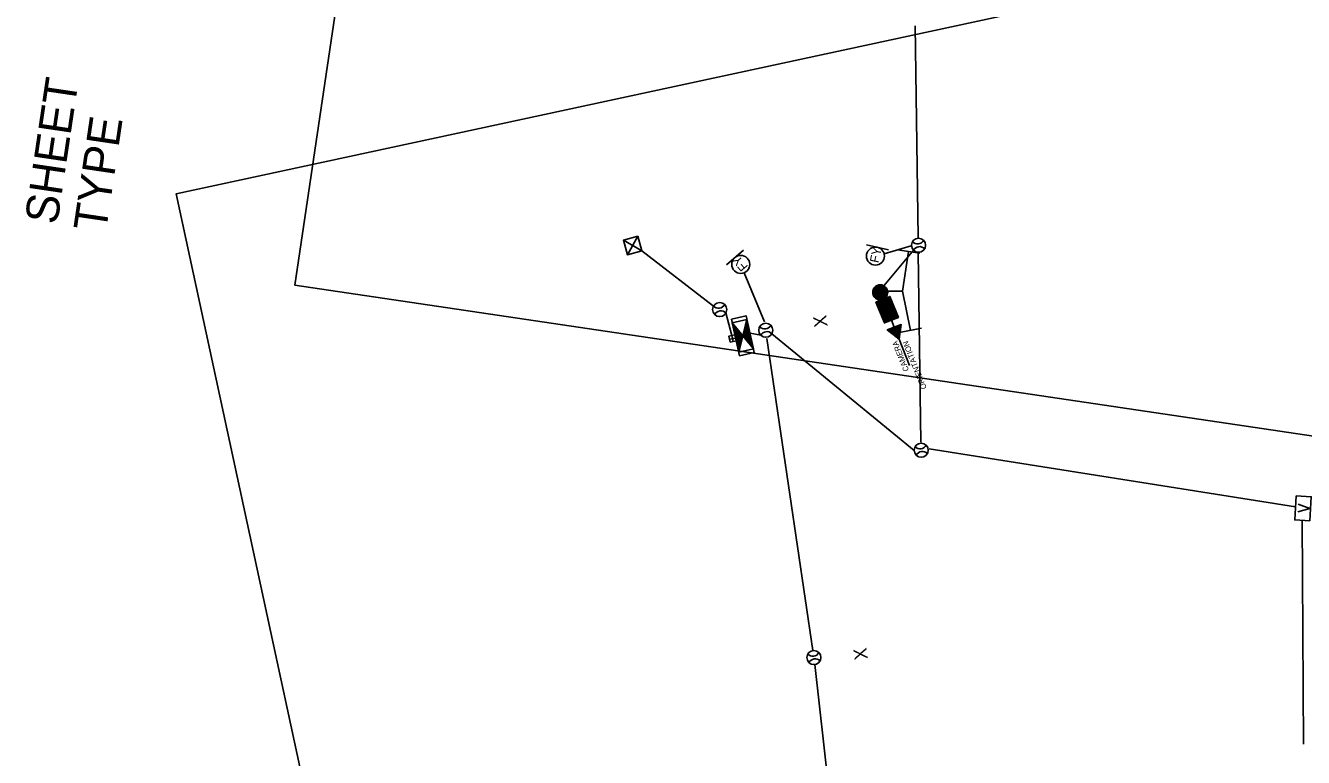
# Model space of a CAD drawing. Extents: x 601462 to 605493, y 331960 to 402715.
# Drawn here: x 601462 to 602143, y 355203 to 355593 of the extents above; entities that cross this region are included whole.
import ezdxf

# ---------------------------------------------------------------- set-up
doc = ezdxf.new("R2010")
doc.units = 0
for name, color, linetype in [('Default', 7, 'Continuous'), ('P_FTMS', 7, 'Continuous'), ('P_FTMSConduit', 7, 'Continuous'), ('P_MISC_TXT_1A', 7, 'Continuous'), ('P_MISC_TXT_2A (Construction)', 7, 'Continuous'), ('P_MISC_TXT_2B (Construction)', 7, 'Continuous')]:
    doc.layers.add(name, color=color, linetype=linetype)

# ---------------------------------------------------------------- blocks, each defined once
blk = doc.blocks.new('FMB_1')
at = {"layer": 'P_FTMS'}
for p, q in [((24.4, -24.4), (-24.4, 24.4)), ((-24.4, -24.4), (24.4, 24.4))]:
    blk.add_line(p, q, dxfattribs=at)
blk.add_lwpolyline([(24.4, -24.4), (24.4, 24.4), (-24.4, 24.4), (-24.4, -24.4)], close=True, dxfattribs=at)
blk = doc.blocks.new('POINT_DISPLAY')
at = {"layer": 'Default'}
blk.add_line((0, 0), (0, 0), dxfattribs=at)
blk = doc.blocks.new('FCS')
at = {"layer": 'P_FTMS'}
for p, q in [((-92.7, 0), (0, 0)), ((1.3, -0.8), (4.9, 2.8)), ((4.9, -2.8), (1.3, 0.8)), ((2.6, -1.5), (9.8, 5.7)), ((9.8, -5.7), (2.6, 1.5)), ((3.9, -2.3), (14.7, 8.5)), ((14.7, -8.5), (3.9, 2.3)), ((5.2, -3), (19.6, 11.3)), ((19.6, -11.3), (5.2, 3)), ((6.6, -3.8), (24.5, 14.1)), ((24.5, -14.2), (6.6, 3.8)), ((7.9, -4.5), (29.4, 17)), ((29.4, -17), (7.9, 4.5)), ((9.2, -5.3), (34.3, 19.8)), ((34.3, -19.8), (9.2, 5.3)), ((10.5, -6.1), (39.2, 22.6)), ((39.2, -22.6), (10.5, 6.1)), ((11.8, -6.8), (42, 23.4)), ((42, -23.4), (11.8, 6.8)), ((13.1, -7.6), (42, 21.3)), ((42, -21.3), (13.1, 7.6)), ((14.4, -8.3), (42, 19.3)), ((42, -19.3), (14.4, 8.3)), ((15.7, -9.1), (42, 17.2)), ((42, -17.2), (15.7, 9.1)), ((17, -9.8), (42, 15.1)), ((42, -15.1), (17.1, 9.8)), ((18.4, -10.6), (42, 13.1)), ((42, -13.1), (18.4, 10.6)), ((42, -11), (19.7, 11.4)), ((19.7, -11.4), (42, 11)), ((42, -8.9), (21, 12.1)), ((21, -12.1), (42, 8.9)), ((42, -6.8), (22.3, 12.9)), ((22.3, -12.9), (42, 6.8)), ((42, -4.8), (23.6, 13.6)), ((23.6, -13.6), (42, 4.8)), ((42, -2.7), (24.9, 14.4)), ((24.9, -14.4), (42, 2.7)), ((42, -0.6), (26.2, 15.1)), ((26.2, -15.2), (42, 0.6)), ((42, 1.4), (27.5, 15.9)), ((42, 3.5), (28.9, 16.7)), ((42, 5.6), (30.2, 17.4)), ((42, 7.6), (31.5, 18.2)), ((42, 9.7), (32.8, 18.9)), ((42, 11.8), (34.1, 19.7)), ((42, 13.8), (35.4, 20.4)), ((42, 15.9), (36.7, 21.2)), ((42, 18), (38, 22)), ((42, 20.1), (39.3, 22.7)), ((42, 22.1), (40.7, 23.5)), ((42, 24.2), (42, 24.2)), ((66.4, 0.1), (42, 0.1)), ((66.4, -24.3), (115.2, 24.5)), ((66.4, -13.9), (104.8, 24.5)), ((66.4, -3.6), (94.5, 24.5)), ((66.4, 6.8), (84.1, 24.5)), ((66.4, 17.1), (73.8, 24.5)), ((66.4, -22.2), (113.1, 24.5)), ((66.4, -11.9), (102.8, 24.5)), ((66.4, -1.5), (92.4, 24.5)), ((66.4, 8.8), (82.1, 24.5)), ((66.4, 19.2), (71.7, 24.5)), ((66.4, -20.1), (111, 24.5)), ((66.4, -9.8), (100.7, 24.5)), ((66.4, 0.6), (90.3, 24.5)), ((66.4, 10.9), (80, 24.5)), ((66.4, 21.2), (69.6, 24.5)), ((66.4, -18.1), (109, 24.5)), ((66.4, -7.7), (98.6, 24.5)), ((66.4, 2.6), (88.3, 24.5)), ((66.4, 13), (77.9, 24.5)), ((66.4, 23.3), (67.6, 24.5)), ((66.4, -16), (106.9, 24.5)), ((66.4, -5.7), (96.5, 24.5)), ((66.4, 4.7), (86.2, 24.5)), ((66.4, 15), (75.9, 24.5)), ((114, -24.3), (66.4, 23.3)), ((111.9, -24.3), (66.4, 21.2)), ((109.9, -24.3), (66.4, 19.2)), ((107.8, -24.3), (66.4, 17.1)), ((105.7, -24.3), (66.4, 15)), ((103.6, -24.3), (66.4, 13)), ((101.6, -24.3), (66.4, 10.9)), ((99.5, -24.3), (66.4, 8.8)), ((97.4, -24.3), (66.4, 6.8)), ((95.4, -24.3), (66.4, 4.7)), ((93.3, -24.3), (66.4, 2.6)), ((91.2, -24.3), (66.4, 0.6)), ((116.1, -24.3), (67.3, 24.5)), ((68.5, -24.3), (117.2, 24.5)), ((118.1, -24.3), (69.4, 24.5)), ((70.5, -24.3), (119.3, 24.5)), ((120.2, -24.3), (71.4, 24.5)), ((72.6, -24.3), (121.4, 24.5)), ((122.3, -24.3), (73.5, 24.5)), ((74.7, -24.3), (123.4, 24.5)), ((124.3, -24.3), (75.6, 24.5)), ((76.7, -24.3), (125.5, 24.5)), ((126.4, -24.3), (77.6, 24.5)), ((78.8, -24.3), (127.6, 24.5)), ((128.5, -24.3), (79.7, 24.5)), ((80.9, -24.3), (129.7, 24.5)), ((130.5, -24.3), (81.8, 24.5)), ((83, -24.3), (131.7, 24.5)), ((132.6, -24.3), (83.8, 24.5)), ((85, -24.3), (133.8, 24.5)), ((134.7, -24.3), (85.9, 24.5)), ((87.1, -24.3), (135.9, 24.5)), ((136.7, -24.3), (88, 24.5)), ((89.2, -24.3), (137.9, 24.5)), ((138.8, -24.3), (90.1, 24.5)), ((91.2, -24.3), (139.6, 24.1)), ((139.6, -22.9), (92.1, 24.5)), ((93.3, -24.3), (139.6, 22)), ((139.6, -20.9), (94.2, 24.5)), ((95.4, -24.3), (139.6, 19.9)), ((139.6, -18.8), (96.3, 24.5)), ((97.4, -24.3), (139.6, 17.8)), ((139.6, -16.7), (98.3, 24.5)), ((99.5, -24.3), (139.6, 15.8)), ((139.6, -14.7), (100.4, 24.5)), ((101.6, -24.3), (139.6, 13.7)), ((139.6, -12.6), (102.5, 24.5)), ((103.6, -24.3), (139.6, 11.6)), ((139.6, -10.5), (104.5, 24.5)), ((105.7, -24.3), (139.6, 9.6)), ((139.6, -8.5), (106.6, 24.5)), ((107.8, -24.3), (139.6, 7.5)), ((139.6, -6.4), (108.7, 24.5)), ((109.9, -24.3), (139.6, 5.4)), ((110.4, 0.1), (112, 0.1)), ((139.6, -4.3), (110.7, 24.5)), ((111.9, -24.3), (139.6, 3.4)), ((139.6, -2.3), (112.8, 24.5)), ((114, -24.3), (139.6, 1.3)), ((139.6, -0.2), (114.9, 24.5)), ((139.6, 1.9), (116.9, 24.5)), ((139.6, 4), (119, 24.5)), ((139.6, 6), (121.1, 24.5)), ((139.6, 8.1), (123.2, 24.5)), ((139.6, 10.2), (125.2, 24.5)), ((139.6, 12.2), (127.3, 24.5)), ((139.6, 14.3), (129.4, 24.5)), ((139.6, 16.4), (131.4, 24.5)), ((139.6, 18.4), (133.5, 24.5)), ((139.6, 20.5), (135.6, 24.5)), ((139.6, 22.6), (137.6, 24.5)), ((139.6, 0.6), (163.5, 24.4)), ((165.5, -24.2), (139.6, 1.6)), ((139.7, -1.4), (165.4, 24.4)), ((139.8, 2.9), (161.2, 24.3)), ((139.8, -3.3), (167.3, 24.2)), ((167.3, -24), (139.9, 3.5)), ((140.1, 5.2), (158.7, 23.9)), ((169.1, -23.7), (140.1, 5.3)), ((140.2, -5), (169.1, 23.9)), ((140.6, -6.7), (170.7, 23.4)), ((170.8, -23.3), (140.6, 6.9)), ((141, 8.2), (155.9, 23.1)), ((141.1, -8.2), (172.3, 23)), ((172.3, -22.7), (141.1, 8.5)), ((141.7, -9.7), (173.8, 22.3)), ((173.8, -22.2), (141.7, 9.9)), ((142.3, -11.1), (175.2, 21.7)), ((175.2, -21.5), (142.4, 11.3)), ((142.7, 12), (152.2, 21.5)), ((143.1, -12.4), (176.5, 20.9)), ((176.5, -20.7), (143.1, 12.7)), ((143.9, -13.7), (177.7, 20.1)), ((177.8, -19.9), (143.9, 13.9)), ((144.8, -14.9), (179, 19.3)), ((178.9, -19), (144.8, 15.1)), ((180.1, -18.1), (145.7, 16.3)), ((145.8, -16), (180.1, 18.3)), ((146.7, -17.1), (181.1, 17.3)), ((181.2, -17.1), (146.8, 17.3)), ((182.1, -16), (147.8, 18.3)), ((147.8, -18.1), (182.2, 16.3)), ((183.1, -14.9), (148.9, 19.3)), ((149, -19), (183.1, 15.1)), ((184, -13.7), (150.1, 20.1)), ((150.1, -19.9), (184, 13.9)), ((184.8, -12.4), (151.4, 20.9)), ((151.4, -20.7), (184.8, 12.7)), ((185.5, -11.2), (152.7, 21.7)), ((152.7, -21.5), (185.5, 11.3)), ((186.2, -9.7), (154.1, 22.3)), ((154.1, -22.2), (186.2, 9.9)), ((186.8, -8.2), (155.6, 23)), ((155.6, -22.7), (186.8, 8.5)), ((157.1, -23.3), (187.3, 6.9)), ((187.3, -6.7), (157.2, 23.4)), ((187.7, -5), (158.8, 23.9)), ((158.8, -23.7), (187.8, 5.3)), ((188.1, -3.3), (160.5, 24.2)), ((160.6, -24), (188, 3.5)), ((188.2, -1.4), (162.4, 24.4)), ((162.4, -24.2), (188.2, 1.6)), ((188.3, 0.6), (164.4, 24.5)), ((188.1, 2.9), (166.7, 24.3)), ((187.8, 5.2), (169.2, 23.9)), ((186.9, 8.2), (172, 23.1)), ((185.2, 12), (175.7, 21.4)), ((27.5, -15.9), (42, -1.4)), ((28.9, -16.7), (42, -3.5)), ((30.2, -17.4), (42, -5.6)), ((31.5, -18.2), (42, -7.6)), ((32.8, -18.9), (42, -9.7)), ((34.1, -19.7), (42, -11.8)), ((35.4, -20.5), (42, -13.8)), ((36.7, -21.2), (42, -15.9)), ((38, -22), (42, -18)), ((39.3, -22.7), (42, -20.1)), ((40.7, -23.5), (42, -22.1)), ((42, -24.2), (42, -24.2)), ((89.2, -24.3), (66.4, -1.5)), ((87.1, -24.3), (66.4, -3.6)), ((85, -24.3), (66.4, -5.7)), ((83, -24.3), (66.4, -7.7)), ((80.9, -24.3), (66.4, -9.8)), ((78.8, -24.3), (66.4, -11.9)), ((76.7, -24.3), (66.4, -13.9)), ((74.7, -24.3), (66.4, -16)), ((72.6, -24.3), (66.4, -18.1)), ((70.5, -24.3), (66.4, -20.1)), ((68.5, -24.3), (66.4, -22.2)), ((116.1, -24.3), (139.6, -0.8)), ((118.1, -24.3), (139.6, -2.8)), ((120.2, -24.3), (139.6, -4.9)), ((122.3, -24.3), (139.6, -7)), ((124.3, -24.3), (139.6, -9.1)), ((126.4, -24.3), (139.6, -11.1)), ((128.5, -24.3), (139.6, -13.2)), ((130.5, -24.3), (139.6, -15.3)), ((132.6, -24.3), (139.6, -17.3)), ((134.7, -24.3), (139.6, -19.4)), ((136.7, -24.3), (139.6, -21.5)), ((138.8, -24.3), (139.6, -23.5)), ((163.4, -24.2), (139.6, -0.4)), ((161.2, -24.1), (139.7, -2.6)), ((158.7, -23.6), (140.2, -5.1)), ((155.8, -22.8), (141, -8)), ((152, -21), (142.7, -11.8)), ((164.5, -24.2), (188.2, -0.4)), ((166.7, -24.1), (188.1, -2.6)), ((169.2, -23.7), (187.7, -5.1)), ((172.1, -22.8), (186.9, -8)), ((175.9, -21), (185.2, -11.8))]:
    blk.add_line(p, q, dxfattribs=at)
for points in [[(42, -24.3), (42, 24.3), (0, 0)], [(139.6, 24.5), (66.4, 24.5), (66.4, -24.3), (139.6, -24.3)]]:
    blk.add_lwpolyline(points, close=True, dxfattribs=at)
blk.add_circle((163.9, 0.1), 24.4, dxfattribs=at)
for p in [(0, 0), (110.4, 0.1)]:
    blk.add_blockref('POINT_DISPLAY', p, dxfattribs=at)
at = {"layer": 'P_MISC_TXT_1A'}
for s, height, p in [('CAMERA', 18.29, (-105.8, 7)), ('ORIENTATION', 18.288, (-181.1, -25))]:
    blk.add_text(s, height=height, rotation=360, dxfattribs=at).set_placement(p)
blk = doc.blocks.new('FTMS_FCV')
at = {"layer": 'P_FTMS'}
blk.add_line((12.7, 16.3), (0.6, -21.9), dxfattribs=at)
blk.add_lwpolyline([(39.1, 24.4), (-39.1, 24.4), (-39.1, -24.4), (39.1, -24.4)], close=True, dxfattribs=at)
blk.add_lwpolyline([(-12.1, 16.2), (0.6, -21.9)], dxfattribs=at)
blk = doc.blocks.new('FTMS_FCB')
at = {"layer": 'P_FTMS'}
for p, q in [((-48.3, 24.1), (-48, 24.4)), ((-45.5, 22.7), (-47.1, 24.4)), ((-46.9, 23.4), (-46, 24.4)), ((-45.5, 22.8), (-43.9, 24.4)), ((-41.4, 20.7), (-45.1, 24.4)), ((-44.1, 22.1), (-41.8, 24.4)), ((-37.2, 18.6), (-43, 24.4)), ((-42.8, 21.4), (-39.8, 24.4)), ((-41.4, 20.7), (-37.7, 24.4)), ((-33.1, 16.5), (-40.9, 24.4)), ((-40, 20), (-35.6, 24.4)), ((-29, 14.5), (-38.9, 24.4)), ((-38.6, 19.3), (-33.6, 24.4)), ((-37.2, 18.6), (-31.5, 24.4)), ((-24.8, 12.4), (-36.8, 24.4)), ((-35.9, 17.9), (-29.4, 24.4)), ((-20.7, 10.3), (-34.7, 24.4)), ((-34.5, 17.2), (-27.3, 24.4)), ((-33.1, 16.5), (-25.3, 24.4)), ((-16.5, 8.3), (-32.7, 24.4)), ((-31.7, 15.9), (-23.2, 24.4)), ((-12.4, 6.2), (-30.6, 24.4)), ((-30.3, 15.2), (-21.1, 24.4)), ((-29, 14.5), (-19.1, 24.4)), ((-8.3, 4.1), (-28.5, 24.4)), ((-27.6, 13.8), (-17, 24.4)), ((-4.1, 2.1), (-26.4, 24.4)), ((-26.2, 13.1), (-14.9, 24.4)), ((-24.8, 12.4), (-12.9, 24.4)), ((0, 0), (-24.4, 24.4)), ((-24.4, -24.4), (0, 0)), ((-23.5, 11.7), (-10.8, 24.4)), ((1.4, 0.7), (-22.3, 24.4)), ((-22.1, 11), (-8.7, 24.4)), ((-20.7, 10.3), (-6.7, 24.4)), ((2.8, 1.4), (-20.2, 24.4)), ((-19.3, 9.7), (-4.6, 24.4)), ((4.1, 2.1), (-18.2, 24.4)), ((-17.9, 9), (-2.5, 24.4)), ((-16.6, 8.3), (-0.4, 24.4)), ((5.5, 2.8), (-16.1, 24.4)), ((-15.2, 7.6), (1.6, 24.4)), ((6.9, 3.4), (-14, 24.4)), ((-13.8, 6.9), (3.7, 24.4)), ((-12.4, 6.2), (5.8, 24.4)), ((8.3, 4.1), (-12, 24.4)), ((-11, 5.5), (7.8, 24.4)), ((9.7, 4.8), (-9.9, 24.4)), ((-9.7, 4.8), (9.9, 24.4)), ((-8.3, 4.1), (12, 24.4)), ((11, 5.5), (-7.8, 24.4)), ((-6.9, 3.4), (14, 24.4)), ((12.4, 6.2), (-5.8, 24.4)), ((-5.5, 2.8), (16.1, 24.4)), ((-4.1, 2.1), (18.2, 24.4)), ((13.8, 6.9), (-3.7, 24.4)), ((-2.8, 1.4), (20.2, 24.4)), ((15.2, 7.6), (-1.6, 24.4)), ((-1.4, 0.7), (22.3, 24.4)), ((0, 0), (24.4, 24.4)), ((24.4, -24.4), (0, 0)), ((16.6, 8.3), (0.4, 24.4)), ((17.9, 9), (2.5, 24.4)), ((4.1, 2.1), (26.5, 24.4)), ((19.3, 9.7), (4.6, 24.4)), ((20.7, 10.3), (6.7, 24.4)), ((8.3, 4.1), (28.5, 24.4)), ((22.1, 11), (8.7, 24.4)), ((23.4, 11.7), (10.8, 24.4)), ((12.4, 6.2), (30.6, 24.4)), ((24.8, 12.4), (12.9, 24.4)), ((26.2, 13.1), (14.9, 24.4)), ((16.6, 8.3), (32.7, 24.4)), ((27.6, 13.8), (17, 24.4)), ((29, 14.5), (19.1, 24.4)), ((20.7, 10.3), (34.7, 24.4)), ((30.3, 15.2), (21.1, 24.4)), ((31.7, 15.9), (23.2, 24.4)), ((24.8, 12.4), (36.8, 24.4)), ((33.1, 16.6), (25.3, 24.4)), ((34.5, 17.2), (27.3, 24.4)), ((29, 14.5), (38.9, 24.4)), ((35.9, 17.9), (29.4, 24.4)), ((37.2, 18.6), (31.5, 24.4)), ((33.1, 16.6), (40.9, 24.4)), ((38.6, 19.3), (33.5, 24.4)), ((40, 20), (35.6, 24.4)), ((37.2, 18.6), (43, 24.4)), ((41.4, 20.7), (37.7, 24.4)), ((42.8, 21.4), (39.8, 24.4)), ((41.4, 20.7), (45.1, 24.4)), ((44.1, 22.1), (41.8, 24.4)), ((45.5, 22.8), (43.9, 24.4)), ((45.5, 22.8), (47.1, 24.4)), ((46.9, 23.5), (46, 24.4)), ((48.3, 24.1), (48, 24.4)), ((-48, -24.4), (-48.3, -24.1)), ((-47.2, -24.4), (-45.5, -22.8)), ((-45.9, -24.4), (-46.9, -23.5)), ((-43.9, -24.4), (-45.5, -22.8)), ((-45.1, -24.4), (-41.4, -20.7)), ((-41.8, -24.4), (-44.1, -22.1)), ((-43, -24.4), (-37.3, -18.6)), ((-39.7, -24.4), (-42.8, -21.4)), ((-37.7, -24.4), (-41.4, -20.7)), ((-41, -24.4), (-33.1, -16.6)), ((-35.6, -24.4), (-40, -20)), ((-38.9, -24.4), (-29, -14.5)), ((-33.5, -24.4), (-38.6, -19.3)), ((-31.5, -24.4), (-37.2, -18.6)), ((-36.8, -24.4), (-24.8, -12.4)), ((-29.4, -24.4), (-35.9, -17.9)), ((-34.8, -24.4), (-20.7, -10.4)), ((-27.3, -24.4), (-34.5, -17.2)), ((-25.3, -24.4), (-33.1, -16.6)), ((-32.7, -24.4), (-16.6, -8.3)), ((-23.2, -24.4), (-31.7, -15.9)), ((-30.6, -24.4), (-12.4, -6.2)), ((-21.1, -24.4), (-30.3, -15.2)), ((-19, -24.4), (-29, -14.5)), ((-28.5, -24.4), (-8.3, -4.1)), ((-17, -24.4), (-27.6, -13.8)), ((-26.5, -24.4), (-4.1, -2.1)), ((-14.9, -24.4), (-26.2, -13.1)), ((-12.8, -24.4), (-24.8, -12.4)), ((-10.8, -24.4), (-23.4, -11.7)), ((-22.3, -24.4), (1.4, -0.7)), ((-8.7, -24.4), (-22.1, -11)), ((-6.6, -24.4), (-20.7, -10.3)), ((-20.3, -24.4), (2.8, -1.4)), ((-4.6, -24.4), (-19.3, -9.7)), ((-18.2, -24.4), (4.1, -2.1)), ((-2.5, -24.4), (-17.9, -9)), ((-0.4, -24.4), (-16.6, -8.3)), ((-16.1, -24.4), (5.5, -2.8)), ((1.6, -24.4), (-15.2, -7.6)), ((-14.1, -24.4), (6.9, -3.4)), ((3.7, -24.4), (-13.8, -6.9)), ((5.8, -24.4), (-12.4, -6.2)), ((-12, -24.4), (8.3, -4.1)), ((7.8, -24.4), (-11, -5.5)), ((-9.9, -24.4), (9.7, -4.8)), ((9.9, -24.4), (-9.7, -4.8)), ((12, -24.4), (-8.3, -4.1)), ((-7.8, -24.4), (11, -5.5)), ((14.1, -24.4), (-6.9, -3.5)), ((-5.8, -24.4), (12.4, -6.2)), ((16.1, -24.4), (-5.5, -2.8)), ((18.2, -24.4), (-4.1, -2.1)), ((-3.7, -24.4), (13.8, -6.9)), ((20.3, -24.4), (-2.8, -1.4)), ((-1.6, -24.4), (15.2, -7.6)), ((22.3, -24.4), (-1.4, -0.7)), ((0.4, -24.4), (16.6, -8.3)), ((2.5, -24.4), (17.9, -9)), ((26.5, -24.4), (4.1, -2.1)), ((4.6, -24.4), (19.3, -9.7)), ((6.6, -24.4), (20.7, -10.3)), ((28.5, -24.4), (8.3, -4.1)), ((8.7, -24.4), (22.1, -11)), ((10.8, -24.4), (23.4, -11.7)), ((30.6, -24.4), (12.4, -6.2)), ((12.8, -24.4), (24.8, -12.4)), ((14.9, -24.4), (26.2, -13.1)), ((32.7, -24.4), (16.6, -8.3)), ((17, -24.4), (27.6, -13.8)), ((19.1, -24.4), (29, -14.5)), ((34.7, -24.4), (20.7, -10.3)), ((21.1, -24.4), (30.3, -15.2)), ((23.2, -24.4), (31.7, -15.9)), ((36.8, -24.4), (24.8, -12.4)), ((25.3, -24.4), (33.1, -16.6)), ((27.3, -24.4), (34.5, -17.2)), ((38.9, -24.4), (29, -14.5)), ((29.4, -24.4), (35.9, -17.9)), ((31.5, -24.4), (37.2, -18.6)), ((40.9, -24.4), (33.1, -16.6)), ((33.5, -24.4), (38.6, -19.3)), ((35.6, -24.4), (40, -20)), ((43, -24.4), (37.2, -18.6)), ((37.7, -24.4), (41.4, -20.7)), ((39.7, -24.4), (42.8, -21.4)), ((45.1, -24.4), (41.4, -20.7)), ((41.8, -24.4), (44.1, -22.1)), ((43.9, -24.4), (45.5, -22.8)), ((47.2, -24.4), (45.5, -22.8)), ((46, -24.4), (46.9, -23.5)), ((48, -24.4), (48.3, -24.1))]:
    blk.add_line(p, q, dxfattribs=at)
for points in [[(61, 24.4), (-61, 24.4), (-61, -24.4), (61, -24.4)], [(48.8, 24.4), (-48.8, 24.4), (-48.8, -24.4), (48.8, -24.4)], [(48.8, 24.4), (0, 0), (-48.8, 24.4)], [(48.8, -24.4), (-48.8, -24.4), (0, 0)]]:
    blk.add_lwpolyline(points, close=True, dxfattribs=at)
blk = doc.blocks.new('FTMS')
at = {"layer": 'P_FTMS'}
for p, q in [((-23, 0), (26, 0)), ((0, 24), (0, -24))]:
    blk.add_line(p, q, dxfattribs=at)
blk.add_lwpolyline([(26, -24), (26, 24), (-23, 24), (-23, -24)], close=True, dxfattribs=at)
blk = doc.blocks.new('FTMS_FERA')
at = {"layer": 'P_FTMS'}
for p, q in [((-65.1, 36.6), (-65.1, -36.6)), ((65.1, 0), (-65.1, 0))]:
    blk.add_line(p, q, dxfattribs=at)
blk = doc.blocks.new('FTMS_FFY')
at = {"layer": 'P_FTMS'}
blk.add_line((36.6, -45.7), (36.6, 45.7), dxfattribs=at)
blk.add_circle((0, 0), 36.6, dxfattribs=at)
blk.add_text('FY', height=36.58, dxfattribs=at).set_placement((-26.8, -18.3))

msp = doc.modelspace()

# ---------------------------------------------------------------- linework, layer by layer
at = {"layer": 'P_FTMS'}
msp.add_line((601921.41, 355451.2), (601929.36, 355451.2), dxfattribs=at)
for centre in [(601937.94, 355475.61), (601831.99, 355441.36), (601856.54, 355430.31), (601939.33, 355366.39), (601882.18, 355255.85)]:
    msp.add_circle(centre, 3.75, dxfattribs=at)
for centre, start, end in [((601937.34, 355480.07), 224.54439, 330.80004), ((601938.54, 355471.15), 44.54439, 150.80004), ((601831.39, 355445.82), 224.54439, 330.80004), ((601832.59, 355436.9), 44.54439, 150.80004), ((601855.94, 355434.77), 224.54439, 330.80004), ((601857.14, 355425.85), 44.54439, 150.80004), ((601938.73, 355370.85), 224.54439, 330.80004), ((601939.93, 355361.93), 44.54439, 150.80004), ((601881.58, 355260.31), 224.54439, 330.80004), ((601882.78, 355251.39), 44.54439, 150.80004)]:
    msp.add_arc(centre, 3.75, start, end, dxfattribs=at)
at = {"layer": 'P_FTMSConduit'}
for p, q in [((601936.12, 355592.53), (601937.64, 355479.81)), ((601828.71, 355443.19), (601790.54, 355472.7)), ((601935.37, 355473.15), (601919.48, 355453.98)), ((601933.96, 355475.39), (601919.54, 355470.99)), ((601937.75, 355471.82), (601939.12, 355370.58)), ((601855.94, 355434.77), (601845.06, 355460.98)), ((601838.47, 355427.48), (601835.26, 355439.53)), ((601853.87, 355427.68), (601848.14, 355428.68)), ((601935.58, 355366.16), (601859.81, 355428.48)), ((602138.79, 355336.24), (601943.53, 355367.05)), ((602142.95, 355209.66), (602142.34, 355329.01)), ((601902.2, 355079.35), (601882.6, 355252.12))]:
    msp.add_line(p, q, dxfattribs=at)
msp.add_lwpolyline([(601881.59, 355259.55), (601857.14, 355425.85)], dxfattribs=at)
at = {"layer": 'P_MISC_TXT_2A (Construction)'}
msp.add_lwpolyline([(602570.08, 355311.27), (602801.22, 356869.22), (601836.78, 357012.31), (601605.64, 355454.36)], close=True, dxfattribs=at)
at = {"layer": 'P_MISC_TXT_2B (Construction)'}
msp.add_lwpolyline([(602827.66, 354169.05), (602495.48, 355708.62), (601542.42, 355502.99), (601874.59, 353963.42)], close=True, dxfattribs=at)

# ---------------------------------------------------------------- block references
at = {"layer": 'P_FTMS'}
for name, p, xscale, yscale, rotation in [('FMB_1', (601785.63, 355475.51), 0.16404166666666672, 0.1640416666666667, 105.22140980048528), ('FTMS_FFY', (601843.22, 355465.42), 0.1312333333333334, 0.13123333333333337, 129.86466640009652), ('FTMS_FFY', (601914.97, 355469.86), 0.1312333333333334, 0.1312333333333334, 77.68700292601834), ('FTMS_FERA', (601930.98, 355461.76), 0.16404166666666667, 0.1640416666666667, -98.71987256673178), ('FCS', (601927.51, 355425.58), 0.1640416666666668, 0.16404166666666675, 111.86873675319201), ('FTMS_FERA', (601931.5, 355440.73), 0.16404166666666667, 0.1640416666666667, 101.55328706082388), ('FTMS_FCB', (601844.32, 355427.41), 0.16404166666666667, 0.1640416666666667, 102.51989930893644), ('FTMS', (601838.83, 355425.85), 0.06561666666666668, 0.06561666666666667, 102.51989930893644), ('FTMS_FCV', (602142.74, 355335.41), 0.1640416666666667, 0.16404166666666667, 86.34463929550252)]:
    msp.add_blockref(name, p, dxfattribs=dict(at, xscale=xscale, yscale=yscale, rotation=rotation))

# ---------------------------------------------------------------- texts
at = {"layer": 'P_FTMSConduit'}
for p in [(601889.5, 355432.47), (601910.93, 355255.15)]:
    msp.add_text('X', height=7, rotation=97.73936, dxfattribs=at).set_placement(p)
at = {"layer": 'P_MISC_TXT_2A (Construction)'}
for s, p in [('SHEET', (601479.07, 355486.23)), ('TYPE', (601505.03, 355482.38))]:
    msp.add_text(s, height=17.5, rotation=81.56113, dxfattribs=at).set_placement(p)

doc.saveas('drawing.dxf')
